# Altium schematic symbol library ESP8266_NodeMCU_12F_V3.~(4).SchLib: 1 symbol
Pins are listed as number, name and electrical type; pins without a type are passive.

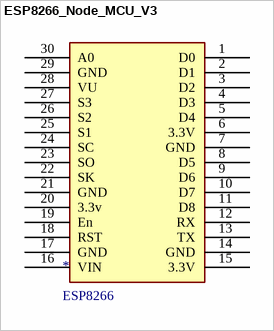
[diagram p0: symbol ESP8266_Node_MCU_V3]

## ESP8266_Node_MCU_V3
designator *, comment ESP8266
footprint Model Name (Model Description)
pins: 1 D0, 2 D1, 3 D2, 4 D3, 5 D4, 6 3.3V, 7 GND, 8 D5, 9 D6, 10 D7, 11 D8, 12 RX, 13 TX, 14 GND, 15 3.3V, 16 VIN, 17 GND, 18 RST, 19 En, 20 3.3v, 21 GND, 22 SK, 23 SO, 24 SC, 25 S1, 26 S2, 27 S3, 28 VU, 29 GND, 30 A0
